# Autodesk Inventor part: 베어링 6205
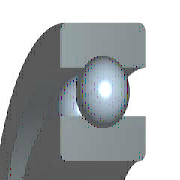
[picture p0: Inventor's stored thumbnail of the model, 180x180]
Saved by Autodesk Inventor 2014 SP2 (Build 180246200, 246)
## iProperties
IsCustomPart: 1
Company: 한국ATC센터
Created: 2014-10
Part Number: 베어링 6205
Material: 강철, 연강
Description: 깊은 그루브 볼 베어링
Document SubType Name: Modeling
Standard: KS B 2023
Designer: 한국ATC센터
Standards Organization: KS
Language: ko-KR
Size Designation: 6205 - 25 x 52 x 15
Categories: <MemberInstance><Categories><Category DisplayName="샤프트 부품" InternalName="7f7aeb1f-a693-4053-b835-cee3144e0d98" Mnemonic="SHFT"><Category DisplayName="베어링" Inter
Density: 7.86 g/cm^3
Mass: 129.543 g
Surface Area: 107.326 cm^2
Volume: 16.4813 cm^3
Appearance: 강철
Author: KYOUNG IL JANG
Revision Number: 1
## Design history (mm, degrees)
sketch "스케치" dims "d0" = 7.02 (= -0.26 x WD + 0.26 x BD)
  geometry: L1 (3.99, 19.25)-(11.01, 19.25); L2 (7.5, 19.25)-(7.5, 15.74); L3 (7.5, 19.25)-(7.5, 22.76); L4 (4.892, 16.901)-(0, 16.901); L5 (0, 12.5)-(15, 12.5); L6 (4.892, 21.599)-(0, 21.599); L7 (0, 26)-(15, 26); L8 (15, 12.5)-(15, 16.901); L9 (10.108, 16.901)-(15, 16.901); L10 (10.108, 21.599)-(15, 21.599); L11 (15, 26)-(15, 21.599); L12 (-1.4, 0)-(8.4, 0) reference; L13 (0, -0.3)-(0, 5.3) reference
  constraints: 22 end point, 4 point on line, 2 collinear, 2 perpendicular, 2 symmetric about line, 1 midpoint, 1 parallel, 14 other
  dimensions: "d9" = 25 diameter of L5 L12 (= WD); "d11" = 52 diameter of L7 L12 (= BD); "d12" = 15 distance between parallel lines of L8 L13 (= KB); "d13" = 33.802 diameter of L9 L12 (= 0.326 x BD + 0.674 x WD)
revolve "본체" stored, may be unused: angle "d6" = 90 deg
revolve "볼" stored, may be unused: angle "d7" = 90 deg
pattern_circular "IDS_ARRAYBALL[SIMPL:T]" dims angle "d3" = 360 deg
body "Solid1"
fillet "모깎기1" dims "d1" = 1 (= KRS)
other parameters: "WD" = 25 [user parameter; used in 5 equation terms], "BD" = 52 [user parameter; used in 5 equation terms], "KB" = 15 [user parameter; used in 1 equation term], "KRS" = 1 [user parameter; used in 1 equation term], "d4" = 0, "d5" = 0, "d8" = 0, "d14" = 0, "d15" = 0, "BBA" = 0 [user parameter], "BC0" = 7800000 [user parameter], "BC" = 1.4e+07 [user parameter], "BR" = 26 (= 0.5 x BD) [user parameter], "WR" = 12.5 (= 0.5 x WD) [user parameter]
